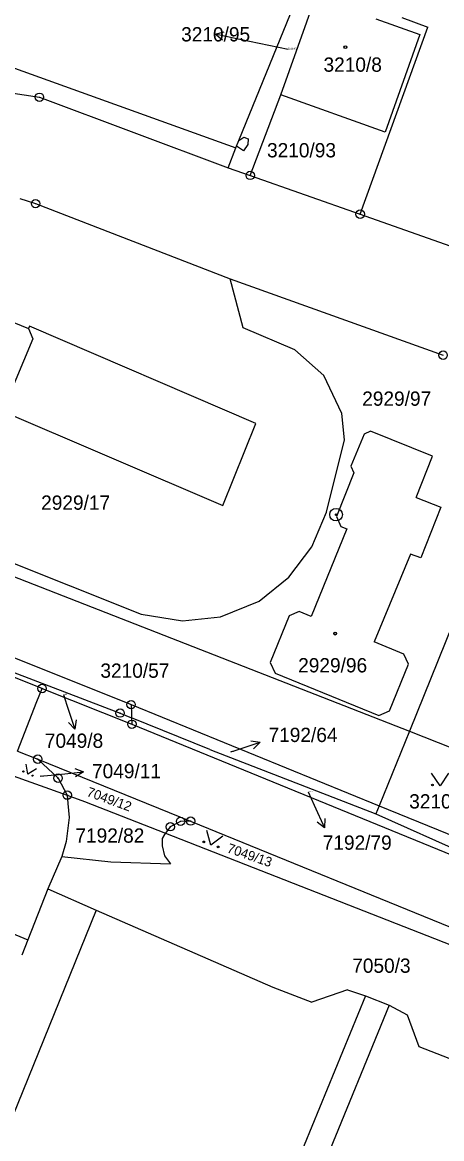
# Model space of a CAD drawing. Extents: x -593183 to -588034, y -1130415 to -1124994.
# Drawn here: x -592055.1 to -592005.2, y -1128267.2 to -1128134.3 of the extents above; entities that cross this region are included whole.
import ezdxf

# ---------------------------------------------------------------- set-up
doc = ezdxf.new("R2010")
doc.units = 0
for name, color, linetype in [('Vrstva 1', 7, 'Continuous'), ('Vrstva 16', 7, 'Continuous'), ('Vrstva 18', 7, 'Continuous'), ('Vrstva 19', 7, 'Continuous'), ('Vrstva 24', 7, 'Continuous'), ('Vrstva 25', 7, 'Continuous'), ('Vrstva 27', 7, 'Continuous'), ('Vrstva 4', 7, 'Continuous')]:
    doc.layers.add(name, color=color, linetype=linetype)

msp = doc.modelspace()

# ---------------------------------------------------------------- linework, layer by layer
at = {"layer": 'Vrstva 1'}
for p, q in [((-592095.34, -1128125.64), (-592029.68, -1128149.23)), ((-592029.68, -1128149.23), (-592022.32, -1128131.15)), ((-592024.34, -1128142.91), (-592020.18, -1128131.28)), ((-592013, -1128133.85), (-592007.75, -1128135.73)), ((-592009.92, -1128133.72), (-592006.82, -1128134.85)), ((-592014.87, -1128157.11), (-592006.82, -1128134.85)), ((-592007.75, -1128135.73), (-592011.91, -1128147.36)), ((-592065.48, -1128141.27), (-592053.08, -1128143.2)), ((-592053.08, -1128143.2), (-592030.58, -1128151.58)), ((-592027.97, -1128152.5), (-592024.34, -1128142.91)), ((-592011.91, -1128147.36), (-592024.34, -1128142.91)), ((-592030.58, -1128151.58), (-592029.68, -1128149.23)), ((-592030.58, -1128151.58), (-592027.97, -1128152.5)), ((-592027.97, -1128152.5), (-592014.87, -1128157.11)), ((-592055.42, -1128155.23), (-592053.54, -1128155.86)), ((-592053.54, -1128155.86), (-592030.35, -1128164.82)), ((-592014.87, -1128157.11), (-591999.24, -1128162.62)), ((-592028.82, -1128170.66), (-592030.35, -1128164.82)), ((-592030.35, -1128164.82), (-592005, -1128173.9)), ((-592063.93, -1128166.82), (-592054.38, -1128170.71)), ((-592054.27, -1128170.44), (-592054.38, -1128170.71)), ((-592027.31, -1128182.02), (-592054.27, -1128170.44)), ((-592022.64, -1128173.28), (-592028.82, -1128170.66)), ((-592019.22, -1128176.3), (-592022.64, -1128173.28)), ((-592017.07, -1128180.84), (-592019.22, -1128176.3)), ((-592058.34, -1128180.23), (-592031.22, -1128191.81)), ((-592016.72, -1128183.97), (-592017.07, -1128180.84)), ((-592031.22, -1128191.81), (-592027.31, -1128182.02)), ((-592014.41, -1128183.29), (-592015.97, -1128187.1)), ((-592013.63, -1128182.96), (-592014.41, -1128183.29)), ((-592006.26, -1128185.91), (-592013.63, -1128182.96)), ((-592018.9, -1128192.59), (-592016.72, -1128183.97)), ((-592008.2, -1128190.84), (-592006.26, -1128185.91)), ((-592015.97, -1128187.1), (-592015.64, -1128187.9)), ((-592015.64, -1128187.9), (-592017.69, -1128193.09)), ((-591996.58, -1128187.88), (-592009.01, -1128218.65)), ((-592008.2, -1128190.84), (-592005.27, -1128192)), ((-592020.64, -1128196.72), (-592018.9, -1128192.59)), ((-592005.27, -1128192), (-592007.66, -1128198.04)), ((-592071.6, -1128194.2), (-592009.01, -1128218.65)), ((-592017.69, -1128193.09), (-592017.19, -1128194.28)), ((-592017.19, -1128194.28), (-592016.47, -1128194.57)), ((-592016.47, -1128194.57), (-592020.7, -1128205)), ((-592060.91, -1128196.8), (-592040.97, -1128204.74)), ((-592023.36, -1128200.32), (-592020.64, -1128196.72)), ((-592008.87, -1128197.57), (-592013.2, -1128208.04)), ((-592007.66, -1128198.04), (-592008.87, -1128197.57)), ((-592026.9, -1128203.19), (-592023.36, -1128200.32)), ((-592031.52, -1128205.03), (-592026.9, -1128203.19)), ((-592040.97, -1128204.74), (-592036.02, -1128205.53)), ((-592023.33, -1128204.91), (-592025.59, -1128210.48)), ((-592022.15, -1128204.4), (-592023.33, -1128204.91)), ((-592020.7, -1128205), (-592022.15, -1128204.4)), ((-592036.02, -1128205.53), (-592031.52, -1128205.03)), ((-592065.75, -1128207.97), (-592043.48, -1128216.5)), ((-592009.68, -1128209.47), (-592013.2, -1128208.04)), ((-592057.97, -1128209.17), (-592042.17, -1128215.5)), ((-592009.11, -1128210.66), (-592009.68, -1128209.47)), ((-592052.77, -1128213.58), (-592060.72, -1128210.43)), ((-592025.59, -1128210.48), (-592024.99, -1128211.77)), ((-592011.37, -1128216.22), (-592009.11, -1128210.66)), ((-592024.99, -1128211.77), (-592012.65, -1128216.78)), ((-592053.38, -1128215.14), (-592052.77, -1128213.58)), ((-592052.77, -1128213.58), (-592042.06, -1128217.83)), ((-592055.69, -1128221.02), (-592053.38, -1128215.14)), ((-592042.17, -1128215.5), (-592042.12, -1128216.65)), ((-592042.17, -1128215.5), (-592012.61, -1128227.55)), ((-592043.48, -1128216.5), (-592042.1, -1128217.06)), ((-592042.12, -1128216.65), (-592042.1, -1128217.06)), ((-592012.65, -1128216.78), (-592011.37, -1128216.22)), ((-592042.1, -1128217.06), (-592042.06, -1128217.83)), ((-592032.77, -1128220.85), (-592042.1, -1128217.06)), ((-592042.06, -1128217.83), (-591999.5, -1128235.21)), ((-592009.01, -1128218.65), (-592012.61, -1128227.55)), ((-592009.01, -1128218.65), (-591987.9, -1128227.07)), ((-592032.77, -1128220.85), (-592012.99, -1128228.49)), ((-592055.69, -1128221.02), (-592053.29, -1128221.99)), ((-592053.29, -1128221.99), (-592050.86, -1128224.25)), ((-592053.29, -1128221.99), (-592035.07, -1128229.36)), ((-592056.76, -1128223.76), (-592049.77, -1128226.27)), ((-592050.86, -1128224.25), (-592049.77, -1128226.27)), ((-592049.77, -1128226.27), (-592047.71, -1128227.01)), ((-592049.77, -1128226.27), (-592049.71, -1128227.25)), ((-592049.71, -1128227.25), (-592049.56, -1128228.93)), ((-592047.71, -1128227.01), (-592038.06, -1128230.79)), ((-592012.61, -1128227.55), (-592012.99, -1128228.49)), ((-592012.61, -1128227.55), (-591998.99, -1128233.11)), ((-592049.56, -1128228.93), (-592049.88, -1128231.78)), ((-592012.99, -1128228.49), (-591997.26, -1128235.55)), ((-592037.49, -1128230.03), (-592038.06, -1128230.79)), ((-592036.27, -1128229.39), (-592037.49, -1128230.03)), ((-592035.07, -1128229.36), (-592036.27, -1128229.39)), ((-592035.07, -1128229.36), (-591980.28, -1128251.74)), ((-592038.45, -1128231.43), (-592038.47, -1128232.32)), ((-592038.19, -1128230.96), (-592038.45, -1128231.43)), ((-592038.06, -1128230.79), (-592038.19, -1128230.96)), ((-592038.06, -1128230.79), (-591998.83, -1128246.15)), ((-592049.88, -1128231.78), (-592050.4, -1128233.58)), ((-592038.47, -1128232.32), (-592038.17, -1128233.48)), ((-592050.4, -1128233.58), (-592052.1, -1128237.44)), ((-592050.4, -1128233.58), (-592044.56, -1128234.21)), ((-592044.56, -1128234.21), (-592037.47, -1128234.43)), ((-592038.17, -1128233.48), (-592037.47, -1128234.43)), ((-592052.1, -1128237.44), (-592054.46, -1128243.48)), ((-592052.1, -1128237.44), (-592046.32, -1128239.96)), ((-592046.32, -1128239.96), (-592056.91, -1128266.12)), ((-592046.32, -1128239.96), (-592025.26, -1128249.13)), ((-592054.46, -1128243.48), (-592055.18, -1128245.31)), ((-592014.24, -1128250.15), (-592039.77, -1128312.31)), ((-592025.26, -1128249.13), (-592020.65, -1128250.92)), ((-592016.38, -1128249.44), (-592020.65, -1128250.92)), ((-592016.38, -1128249.44), (-592014.24, -1128250.15)), ((-592014.24, -1128250.15), (-592011.43, -1128251.27)), ((-592011.43, -1128251.27), (-592036.9, -1128313.48)), ((-592011.43, -1128251.27), (-592009.27, -1128252.42)), ((-592009.27, -1128252.42), (-592007.9, -1128256.18)), ((-592007.9, -1128256.18), (-591975.11, -1128269.03))]:
    msp.add_line(p, q, dxfattribs=at)
at = {"layer": 'Vrstva 16'}
for p, q in [((-592023.47, -1128137.51), (-592029.22, -1128136.3)), ((-592050.22, -1128214.3), (-592049.8, -1128215.57)), ((-592030.3, -1128221.12), (-592029.64, -1128220.9)), ((-592052.99, -1128224.03), (-592050.82, -1128223.81)), ((-592021.06, -1128225.88), (-592020.35, -1128227.45))]:
    msp.add_line(p, q, dxfattribs=at)
at = {"layer": 'Vrstva 24'}
for centre, radius in [((-592053.08, -1128143.2), 0.5), ((-592053.08, -1128143.2), 0.0327), ((-592027.97, -1128152.5), 0.5), ((-592027.97, -1128152.5), 0.0327), ((-592053.54, -1128155.86), 0.5), ((-592053.54, -1128155.86), 0.0327), ((-592014.87, -1128157.11), 0.5), ((-592014.87, -1128157.11), 0.0327), ((-592005, -1128173.9), 0.5), ((-592017.74, -1128192.88), 0.75), ((-592017.74, -1128192.88), 0.0903), ((-592052.77, -1128213.58), 0.5), ((-592052.77, -1128213.58), 0.0327), ((-592042.17, -1128215.5), 0.5), ((-592042.17, -1128215.5), 0.0327), ((-592043.48, -1128216.5), 0.5), ((-592043.48, -1128216.5), 0.0327), ((-592042.06, -1128217.83), 0.5), ((-592042.06, -1128217.83), 0.0327), ((-592053.29, -1128221.99), 0.5), ((-592053.29, -1128221.99), 0.0327), ((-592050.86, -1128224.25), 0.5), ((-592050.86, -1128224.25), 0.0327), ((-592049.77, -1128226.27), 0.5), ((-592049.77, -1128226.27), 0.0327), ((-592036.27, -1128229.39), 0.5), ((-592035.07, -1128229.36), 0.5), ((-592037.49, -1128230.03), 0.5), ((-592037.49, -1128230.03), 0.0327), ((-592036.27, -1128229.39), 0.0327), ((-592035.07, -1128229.36), 0.0327)]:
    msp.add_circle(centre, radius, dxfattribs=at)
at = {"layer": 'Vrstva 25'}
for p, q in [((-592029.22, -1128136.3), (-592032.16, -1128135.68)), ((-592049.8, -1128215.57), (-592048.85, -1128218.42)), ((-592029.64, -1128220.9), (-592026.79, -1128219.95)), ((-592050.82, -1128223.81), (-592047.84, -1128223.51)), ((-592020.35, -1128227.45), (-592019.12, -1128230.18))]:
    msp.add_line(p, q, dxfattribs=at)
for points in [[(-592031.28, -1128136.38), (-592032.16, -1128135.68), (-592031.07, -1128135.4)], [(-592048.69, -1128217.31), (-592048.85, -1128218.42), (-592049.64, -1128217.63)], [(-592027.9, -1128219.79), (-592026.79, -1128219.95), (-592027.58, -1128220.74)], [(-592053.45, -1128223.12), (-592054.48, -1128223.76), (-592054.67, -1128222.57)], [(-592048.88, -1128223.11), (-592047.84, -1128223.51), (-592048.78, -1128224.11)], [(-592004.36, -1128223.66), (-592005.36, -1128225.16), (-592006.36, -1128223.66)], [(-592019.07, -1128229.07), (-592019.12, -1128230.18), (-592019.98, -1128229.48)], [(-592031.24, -1128231.14), (-592032.68, -1128232.23), (-592033.13, -1128230.49)]]:
    msp.add_lwpolyline(points, dxfattribs=at)
for centre, radius in [((-592016.63, -1128137.23), 0.175), ((-592016.63, -1128137.23), 0.15), ((-592017.85, -1128207.04), 0.175), ((-592017.85, -1128207.04), 0.15), ((-592055, -1128223.45), 0.067), ((-592053.9, -1128223.95), 0.067), ((-592006.26, -1128225.06), 0.1), ((-592033.5, -1128231.84), 0.1), ((-592031.8, -1128232.43), 0.1)]:
    msp.add_circle(centre, radius, dxfattribs=at)
at = {"layer": 'Vrstva 27'}
for p, q in [((-592029.59, -1128149), (-592029.31, -1128148.33)), ((-592028.78, -1128149.58), (-592029.59, -1128149)), ((-592029.31, -1128148.33), (-592028.75, -1128147.96)), ((-592028.24, -1128148.81), (-592028.78, -1128149.58)), ((-592028.75, -1128147.96), (-592028.22, -1128148.14)), ((-592028.22, -1128148.14), (-592028.24, -1128148.81))]:
    msp.add_line(p, q, dxfattribs=at)
at = {"layer": 'Vrstva 4'}
for p, q in [((-592054.38, -1128170.71), (-592053.87, -1128171.95)), ((-592053.87, -1128171.95), (-592057, -1128179.46)), ((-592066.1, -1128238.74), (-592054.46, -1128243.48))]:
    msp.add_line(p, q, dxfattribs=at)

# ---------------------------------------------------------------- texts
at = {"layer": 'Vrstva 16'}
for s, p in [('3210/95', (-592036.2, -1128136.55)), ('7192/64', (-592025.79, -1128219.95)), ('7049/8', (-592052.44, -1128220.64)), ('7049/11', (-592046.82, -1128224.26)), ('7192/79', (-592019.33, -1128232.77))]:
    msp.add_text(s, height=1.7, dxfattribs=at).set_placement(p)
at = {"layer": 'Vrstva 18'}
for s, height, p in [('3210/95', 0.2, (-592023.47, -1128137.51)), ('3210/93', 1.7, (-592025.97, -1128150.35)), ('2929/97', 1.7, (-592014.63, -1128179.92)), ('2929/17', 1.7, (-592052.88, -1128192.3)), ('3210/57', 1.7, (-592045.82, -1128212.3)), ('7049/8', 0.1, (-592050.22, -1128214.3)), ('7192/64', 0.1, (-592030.3, -1128221.12)), ('7049/11', 0.1, (-592052.99, -1128224.03)), ('7192/79', 0.1, (-592021.06, -1128225.88)), ('3210/3', 1.7, (-592009.03, -1128227.86)), ('7192/82', 1.7, (-592048.8, -1128231.93)), ('7050/3', 1.7, (-592015.82, -1128247.42))]:
    msp.add_text(s, height=height, dxfattribs=at).set_placement(p)
for s, rotation, p in [('7049/12', 339.889, (-592047.54, -1128226.34)), ('7049/13', 340.8577, (-592030.82, -1128233.05))]:
    msp.add_text(s, height=1.14, rotation=rotation, dxfattribs=at).set_placement(p)
at = {"layer": 'Vrstva 19'}
for s, p in [('3210/8', (-592019.24, -1128140.16)), ('2929/96', (-592022.26, -1128211.66))]:
    msp.add_text(s, height=1.7, dxfattribs=at).set_placement(p)

doc.saveas('drawing.dxf')
